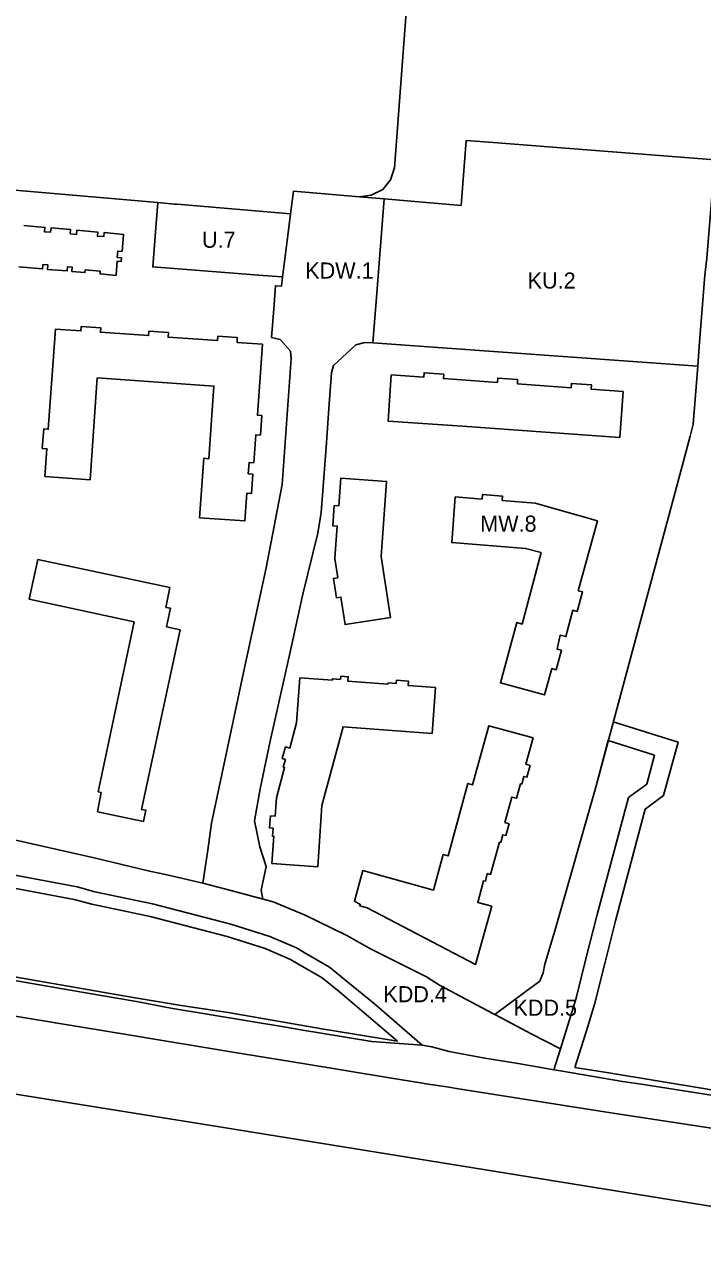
# Model space of a CAD drawing. Extents: x 7427060 to 7429122, y 5545301 to 5546237.
# Drawn here: x 7428012.9 to 7428222.9, y 5545328.8 to 5545710.8 of the extents above; entities that cross this region are included whole.
import ezdxf

# ---------------------------------------------------------------- set-up
doc = ezdxf.new("R2010")
doc.units = 0
for name, color, linetype in [('LIN_Linia Zabudowy Nieprzekraczalna', 7, 'Continuous'), ('LIN_Linia Zabudowy Obowiązujaca', 7, 'Continuous'), ('LIN_Linie Rozgraniczajace', 7, 'Continuous'), ('TXT_Oznaczenia Przeznaczenia', 7, 'Continuous')]:
    doc.layers.add(name, color=color, linetype=linetype)

msp = doc.modelspace()

# ---------------------------------------------------------------- linework, layer by layer
at = {"layer": 'LIN_Linia Zabudowy Nieprzekraczalna'}
for p, q in [((7428028.24, 5545439.5), (7428008.54, 5545443.17)), ((7428033.68, 5545437.97), (7428028.24, 5545439.5)), ((7428051.77, 5545434.17), (7428033.68, 5545437.97)), ((7428075.71, 5545427.94), (7428051.77, 5545434.17)), ((7428087.48, 5545424.26), (7428075.71, 5545427.94)), ((7428095.32, 5545420.85), (7428087.48, 5545424.26)), ((7428097.56, 5545419.55), (7428095.32, 5545420.85)), ((7428105.1, 5545415.17), (7428097.56, 5545419.55)), ((7428110.46, 5545410.78), (7428105.1, 5545415.17)), ((7428128.5, 5545395.56), (7428110.46, 5545410.78))]:
    msp.add_line(p, q, dxfattribs=at)
msp.add_lwpolyline([(7428195.35, 5545494.59), (7428215.4, 5545488.27), (7428210.93, 5545471.68), (7428205.26, 5545467.51), (7428196.02, 5545432.89), (7428192.78, 5545420.02), (7428189.59, 5545407.31), (7428187.42, 5545400.07), (7428183.42, 5545387.33)], dxfattribs=at)
at = {"layer": 'LIN_Linia Zabudowy Obowiązujaca'}
for points in [[(7428011.09, 5545635.74), (7428018.47, 5545635.07), (7428018.58, 5545636.4), (7428020.07, 5545636.28), (7428019.96, 5545634.93), (7428026.06, 5545634.42), (7428026.16, 5545635.74), (7428027.63, 5545635.61), (7428027.51, 5545634.27), (7428031.6, 5545633.93), (7428031.7, 5545634.77), (7428036.36, 5545634.35), (7428036.3, 5545633.53), (7428041.23, 5545633.07), (7428041.24, 5545633.19), (7428041.61, 5545637.5), (7428042.85, 5545637.4), (7428042.95, 5545638.49), (7428041.6, 5545638.61), (7428041.77, 5545640.58), (7428043.12, 5545640.47), (7428043.58, 5545645.79), (7428037.53, 5545646.35), (7428037.44, 5545645.07), (7428035.48, 5545645.22), (7428035.57, 5545646.51), (7428029.09, 5545647.08), (7428028.98, 5545645.79), (7428027.05, 5545645.97), (7428027.16, 5545647.26), (7428021.08, 5545647.79), (7428020.96, 5545646.47), (7428019.04, 5545646.61), (7428019.16, 5545647.96), (7428012.67, 5545648.53)], [(7427864.22, 5545441.69), (7427881.49, 5545438.5), (7427892.83, 5545436.53), (7427906.47, 5545434), (7427917.21, 5545432.18), (7427987.92, 5545419.25), (7428003.13, 5545416.58), (7428046.56, 5545409.04), (7428061.43, 5545406.58), (7428075.93, 5545404.37), (7428104.97, 5545399.32), (7428128.5, 5545395.56)], [(7428183.42, 5545387.33), (7428193.92, 5545385.7), (7428223.31, 5545380.89), (7428238.16, 5545378.37), (7428296.24, 5545368.97)]]:
    msp.add_lwpolyline(points, dxfattribs=at)
for points in [[(7428019.16, 5545570.65), (7428033.18, 5545569.63), (7428035.38, 5545601.23), (7428071.54, 5545598.72), (7428069.97, 5545576.2), (7428068.42, 5545576.31), (7428067.12, 5545557.87), (7428081.15, 5545556.89), (7428081.75, 5545565.5), (7428083.18, 5545565.4), (7428083.61, 5545571.44), (7428082.2, 5545571.54), (7428082.44, 5545575.02), (7428083.95, 5545574.92), (7428084.57, 5545583.62), (7428085.97, 5545583.52), (7428086.41, 5545589.56), (7428085.05, 5545589.66), (7428086.58, 5545611.72), (7428078.72, 5545612.27), (7428078.82, 5545613.74), (7428072.76, 5545614.18), (7428072.67, 5545612.81), (7428057.36, 5545613.88), (7428057.46, 5545615.29), (7428051.42, 5545615.72), (7428051.32, 5545614.36), (7428036.41, 5545615.4), (7428036.5, 5545616.8), (7428030.45, 5545617.22), (7428030.35, 5545615.83), (7428022.48, 5545616.39), (7428021.45, 5545602.21), (7428020.23, 5545585.34), (7428018.82, 5545585.44), (7428018.37, 5545579.36), (7428019.79, 5545579.26)], [(7428126.55, 5545602.18), (7428125.53, 5545587.84), (7428150.05, 5545586.16), (7428172.88, 5545584.58), (7428197.4, 5545582.82), (7428198.4, 5545597.02), (7428188.5, 5545597.72), (7428188.6, 5545599.09), (7428182.35, 5545599.55), (7428182.25, 5545598.22), (7428173.92, 5545598.82), (7428165.61, 5545599.42), (7428165.7, 5545600.76), (7428159.51, 5545601.21), (7428159.42, 5545599.87), (7428151.06, 5545600.46), (7428142.73, 5545601.04), (7428142.82, 5545602.41), (7428136.7, 5545602.84), (7428136.59, 5545601.46)], [(7428126.34, 5545526.89), (7428123.38, 5545545.84), (7428125.08, 5545569.12), (7428110.85, 5545570.13), (7428110.23, 5545561.54), (7428108.84, 5545561.65), (7428108.39, 5545555.42), (7428109.78, 5545555.32), (7428109.17, 5545546.82), (7428109.05, 5545545.25), (7428109.96, 5545539.25), (7428108.59, 5545539.05), (7428109.51, 5545533.06), (7428110.86, 5545533.27), (7428112.24, 5545524.72)], [(7428146.36, 5545564.34), (7428145.26, 5545550.18), (7428168.17, 5545548.36), (7428172.98, 5545547.05), (7428167.1, 5545524.9), (7428165.47, 5545525.37), (7428160.35, 5545506.69), (7428174.06, 5545502.93), (7428176.31, 5545511.11), (7428177.69, 5545510.74), (7428179.29, 5545516.76), (7428177.92, 5545517.13), (7428178.92, 5545521.5), (7428180.59, 5545521.03), (7428182.84, 5545529.21), (7428184.19, 5545528.85), (7428185.81, 5545534.87), (7428184.47, 5545535.23), (7428190.42, 5545556.96), (7428171.1, 5545562.37), (7428160.91, 5545563.19), (7428161.02, 5545564.56), (7428154.78, 5545565.05), (7428154.68, 5545563.66)], [(7428016.97, 5545544.92), (7428014.33, 5545532.61), (7428046.87, 5545525.59), (7428035.73, 5545472.88), (7428036.63, 5545472.63), (7428035.44, 5545466.67), (7428049.78, 5545463.71), (7428050.51, 5545467.14), (7428049.13, 5545467.38), (7428061.08, 5545523.15), (7428056.85, 5545524.06), (7428058.14, 5545529.83), (7428056.68, 5545530.06), (7428057.94, 5545536.2)], [(7428089.48, 5545450.63), (7428103.72, 5545449.59), (7428105.06, 5545468.59), (7428111.58, 5545493.04), (7428139.24, 5545490.98), (7428140.26, 5545505.18), (7428131.78, 5545505.84), (7428131.87, 5545507.24), (7428128.12, 5545507.49), (7428128.04, 5545506.45), (7428125.61, 5545506.68), (7428125.51, 5545506.29), (7428113.1, 5545507.16), (7428113.2, 5545508.55), (7428110.87, 5545508.73), (7428110.78, 5545507.75), (7428108.31, 5545507.95), (7428108.27, 5545507.55), (7428098.23, 5545508.19), (7428097.17, 5545494.23), (7428095.08, 5545486.44), (7428093.73, 5545486.81), (7428092.76, 5545483.16), (7428093.73, 5545482.89), (7428093.07, 5545480.55), (7428093.47, 5545480.4), (7428090.97, 5545470.96), (7428090.54, 5545465.28), (7428089.15, 5545465.39), (7428088.84, 5545461.67), (7428089.9, 5545461.56), (7428089.68, 5545459.11), (7428090.09, 5545459.11)], [(7428170.5, 5545489.57), (7428156.74, 5545493.36), (7428151.69, 5545475.02), (7428150.27, 5545475.46), (7428144.14, 5545453.01), (7428142.65, 5545453.45), (7428139.59, 5545442.4), (7428117.69, 5545448.44), (7428115.09, 5545438.95), (7428116.93, 5545437.96), (7428116.84, 5545437.49), (7428119.02, 5545436.85), (7428152.63, 5545419.3), (7428157.65, 5545437.38), (7428153.31, 5545438.58), (7428155.16, 5545445.28), (7428155.7, 5545445.12), (7428156.3, 5545447.53), (7428157.3, 5545447.24), (7428157.82, 5545449.07), (7428160.1, 5545457.21), (7428160.48, 5545457.16), (7428161.08, 5545459.55), (7428162.07, 5545459.33), (7428163.07, 5545462.92), (7428161.75, 5545463.35), (7428163.93, 5545471.25), (7428165.35, 5545470.88), (7428166.58, 5545475.33), (7428166.99, 5545475.29), (7428167.64, 5545477.63), (7428168.58, 5545477.39), (7428169.57, 5545481.03), (7428168.28, 5545481.42)]]:
    msp.add_lwpolyline(points, close=True, dxfattribs=at)
at = {"layer": 'LIN_Linie Rozgraniczajace'}
for p, q in [((7428156.72, 5545674.4), (7428226.81, 5545668.9)), ((7428122.02, 5545627.56), (7428124.38, 5545656.77)), ((7428124.38, 5545656.77), (7428148.19, 5545654.7)), ((7428122.02, 5545627.56), (7428122.02, 5545627.56)), ((7428120.77, 5545612.12), (7428221.53, 5545604.88)), ((7428217.09, 5545575.48), (7428219.17, 5545583.22)), ((7428195.06, 5545493.51), (7428217.09, 5545575.48)), ((7428189.89, 5545474.29), (7428195.06, 5545493.51)), ((7428193.79, 5545488.79), (7428189.89, 5545474.29)), ((7428208.11, 5545484.27), (7428193.79, 5545488.79)), ((7428205.69, 5545475.27), (7428208.11, 5545484.27)), ((7428200.01, 5545471.1), (7428205.69, 5545475.27)), ((7428189.89, 5545474.29), (7428177.27, 5545429.79)), ((7428069.63, 5545454.74), (7428068.18, 5545444.56)), ((7428177.27, 5545429.79), (7428174.1, 5545419.38)), ((7428174.1, 5545419.38), (7428173.58, 5545416.75)), ((7428172.6, 5545414.17), (7428168.33, 5545411.01)), ((7428173.58, 5545416.75), (7428172.6, 5545414.17)), ((7428025.25, 5545411.66), (7428037.23, 5545409.59)), ((7428168.33, 5545411.01), (7428158.6, 5545403.81)), ((7428037.23, 5545409.59), (7428047.53, 5545407.78)), ((7428047.53, 5545407.78), (7428048.68, 5545407.58)), ((7428048.68, 5545407.58), (7428056.03, 5545406.16)), ((7428056.03, 5545406.16), (7428058.16, 5545405.8)), ((7428158.05, 5545404.11), (7428158.6, 5545403.81)), ((7428158.6, 5545403.81), (7428162.33, 5545401.83)), ((7428162.33, 5545401.83), (7428169.94, 5545397.83)), ((7428178.94, 5545393.1), (7428176.92, 5545386.67))]:
    msp.add_line(p, q, dxfattribs=at)
for points in [[(7428116.68, 5545657.44), (7428120.34, 5545657.9), (7428123.9, 5545659.7), (7428126.25, 5545662.7), (7428127.49, 5545666.41), (7428133.04, 5545739.52), (7428109.44, 5545741.31), (7428109.72, 5545744.4), (7428088.89, 5545746.07), (7428019.26, 5545751.65), (7427969.3, 5545755.66), (7427912.09, 5545760.24), (7427900.08, 5545761.2)], [(7428148.19, 5545654.7), (7428149.79, 5545674.93), (7428156.72, 5545674.4)], [(7428226.81, 5545668.9), (7428224.36, 5545638.35), (7428223.7, 5545633.15), (7428222, 5545611.03), (7428221.53, 5545604.88)], [(7427893.51, 5545606.03), (7427896.79, 5545604.25), (7427899.66, 5545603.83), (7427906.63, 5545603.24), (7427913.4, 5545608.09), (7427953.99, 5545604.63), (7427958.35, 5545657.26), (7427958.6, 5545660.36), (7427961.73, 5545662.33), (7427965.32, 5545663.18), (7427978.67, 5545662.14), (7428054.16, 5545655.62), (7428053.66, 5545649.13), (7428052.6, 5545635.68), (7428085.46, 5545633.14), (7428089.64, 5545632.82), (7428092.85, 5545632.57), (7428092.48, 5545629.68), (7428090.62, 5545629.82), (7428090.11, 5545622.67)], [(7428124.38, 5545656.77), (7428116.68, 5545657.44), (7428096.24, 5545659.21), (7428095.34, 5545652.11), (7428094.7, 5545647.09), (7428093.36, 5545636.55), (7428092.85, 5545632.57)], [(7428095.34, 5545652.11), (7428060.15, 5545655.1), (7428059.33, 5545655.17), (7428054.16, 5545655.62)], [(7428122.02, 5545627.56), (7428120.77, 5545612.12), (7428118.37, 5545612.29), (7428115.59, 5545611.55), (7428108.67, 5545605.12), (7428108.04, 5545602.83), (7428107.22, 5545591.74), (7428106.43, 5545581.16), (7428104.78, 5545559.47), (7428103.8, 5545553.07), (7428099.14, 5545534.17), (7428095.26, 5545516.67), (7428089.02, 5545488.59), (7428085.86, 5545473.75), (7428084.15, 5545463.84), (7428085.77, 5545455.81), (7428087.73, 5545449.73), (7428086.19, 5545442.37), (7428086.77, 5545439.59)], [(7428090.11, 5545622.67), (7428089.46, 5545613.75), (7428092.06, 5545613.18), (7428095.25, 5545609.56), (7428095.53, 5545607.3), (7428094.49, 5545592.79), (7428092.73, 5545568.15), (7428087.72, 5545542.39)], [(7428219.17, 5545583.22), (7428220.15, 5545586.88), (7428221.53, 5545604.88)], [(7428069.63, 5545454.74), (7428070.83, 5545463.18), (7428080.78, 5545509.83), (7428087.72, 5545542.39)], [(7427875.8, 5545488.15), (7427908.91, 5545480.54), (7427937.17, 5545474.62), (7427969.6, 5545467.63), (7427994.01, 5545461.68), (7428000.1, 5545460.2), (7428002.72, 5545459.56), (7428034.43, 5545452.34), (7428051.59, 5545448.3), (7428054.59, 5545447.59), (7428058.78, 5545446.66), (7428068.18, 5545444.56), (7428075.27, 5545442.69), (7428089.91, 5545438.74), (7428099.87, 5545434.57), (7428112.8, 5545428.34), (7428120.06, 5545424.14), (7428137.4, 5545415.49), (7428141.53, 5545412.9), (7428158.05, 5545404.11)], [(7428186.96, 5545421.48), (7428190.21, 5545434.4), (7428200.01, 5545471.1)], [(7428113.02, 5545413.86), (7428107.39, 5545418.47), (7428099.57, 5545423.01), (7428097.13, 5545424.43), (7428088.88, 5545428.01), (7428076.81, 5545431.79), (7428052.58, 5545438.14), (7428049.54, 5545438.77), (7428034.63, 5545441.86), (7428029.15, 5545443.4), (7428009.34, 5545447.09), (7427991.36, 5545451.07)], [(7428225.77, 5545368.53), (7428196.66, 5545372.94), (7428192.6, 5545373.56), (7428147.37, 5545380.77), (7428143.72, 5545381.35), (7428137.2, 5545382.34), (7428135.59, 5545382.6), (7428126.02, 5545384.18), (7428099.12, 5545388.6), (7428081.24, 5545391.54), (7428078.08, 5545392.06), (7428045.68, 5545397.36), (7428022.45, 5545401.16), (7428002.36, 5545404.57), (7427973.33, 5545409.48), (7427924.3, 5545417.53), (7427893.37, 5545424.24), (7427862.15, 5545431.47), (7427856.74, 5545432.41), (7427846.3, 5545434.24), (7427829.57, 5545437.17), (7427808.75, 5545440.81), (7427744.57, 5545442.93)], [(7428169.94, 5545397.83), (7428178.94, 5545393.1), (7428181.68, 5545401.83), (7428183.8, 5545408.9), (7428186.96, 5545421.48)], [(7427975.72, 5545420.24), (7428001.9, 5545415.7), (7428025.25, 5545411.66)], [(7427780.19, 5545413.81), (7427861.1, 5545402.15), (7427931.36, 5545391.73), (7428070.75, 5545369.4), (7428321.97, 5545328.77)], [(7428136.15, 5545394.33), (7428121.29, 5545407.07), (7428113.02, 5545413.86)], [(7428058.16, 5545405.8), (7428093.84, 5545399.87), (7428098.52, 5545399.08)], [(7428098.52, 5545399.08), (7428120.48, 5545395.38), (7428136.15, 5545394.33)], [(7428136.15, 5545394.33), (7428139.08, 5545393.77), (7428144.49, 5545392.27), (7428155.56, 5545390.3), (7428165.81, 5545388.56), (7428171.77, 5545387.56), (7428176.92, 5545386.67)], [(7428321.46, 5545385.45), (7428298.76, 5545389.03), (7428296.16, 5545368.3), (7428254.28, 5545374.29), (7428251.6, 5545374.71), (7428244.03, 5545372.76), (7428230.31, 5545378.06), (7428204.73, 5545382.1), (7428198.2, 5545383.06), (7428178.97, 5545386.33), (7428176.92, 5545386.67)]]:
    msp.add_lwpolyline(points, dxfattribs=at)

# ---------------------------------------------------------------- texts
at = {"layer": 'TXT_Oznaczenia Przeznaczenia'}
for s, p in [('U.7', (7428067.87, 5545641.62)), ('KDW.1', (7428099.87, 5545632.06)), ('MW.8', (7428154.11, 5545553.55)), ('KDD.4', (7428124.08, 5545407.6))]:
    msp.add_text(s, height=5, rotation=360, dxfattribs=at).set_placement(p)
for s, p in [('KU.2', (7428168.81, 5545628.98)), ('KDD.5', (7428164.4, 5545403.4))]:
    msp.add_text(s, height=5, dxfattribs=at).set_placement(p)

doc.saveas('drawing.dxf')
